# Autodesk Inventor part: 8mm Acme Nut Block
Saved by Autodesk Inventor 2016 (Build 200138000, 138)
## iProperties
Created: 2015-11
Part Number: 8mm Acme Nut Block
Material: Generic
Document SubType Name: Modeling
Designer: John
Density: 1 g/cm^3
Appearance: Default
Author: John
Revision Number: ANY
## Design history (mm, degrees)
feature "Cut-Extrude4"
body "Solid1"
